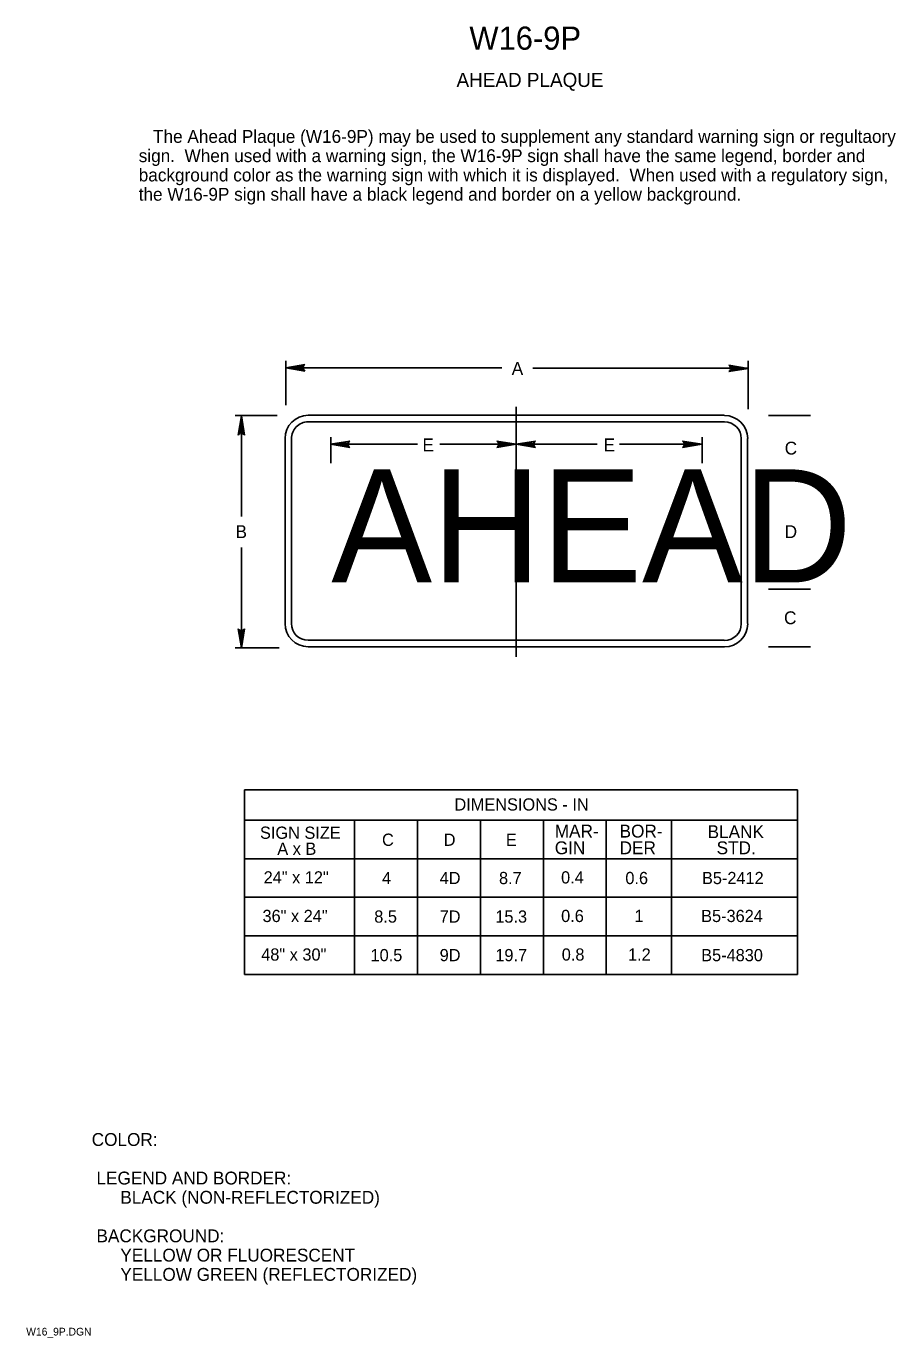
# Model space of a CAD drawing. Extents: x 0.013 to 0.182, y 0.004 to 0.259.
import ezdxf

# ---------------------------------------------------------------- set-up
doc = ezdxf.new("R2010")
doc.units = 0
for name, color, linetype in [('1', 7, 'Continuous'), ('2', 7, 'Continuous'), ('3', 7, 'Continuous')]:
    doc.layers.add(name, color=color, linetype=linetype)

# ---------------------------------------------------------------- blocks, each defined once
blk = doc.blocks.new('RARROW')
at = {"layer": '3'}
for p, q in [((-2.156, 0.285), (-2.2665, 0.384625)), ((-2.2665, 0.384625), (0, 0)), ((0, 0), (-2.2665, -0.379125)), ((-2.156, 0.285), (-2.075625, 0.12075)), ((0, 0), (-2.156, 0.285)), ((-2.14975, -0.2705), (0, 0)), ((-2.075625, 0.12075), (0, 0)), ((0, 0), (-2.074, -0.108)), ((-2.2665, -0.379125), (-2.14975, -0.2705)), ((-2.074, -0.108), (-2.14975, -0.2705))]:
    blk.add_line(p, q, dxfattribs=at)

msp = doc.modelspace()

# ---------------------------------------------------------------- linework, layer by layer
at = {"layer": '1'}
msp.add_line((0.108, 0.185), (0.108, 0.13637), dxfattribs=at)
at = {"layer": '3'}
for p, q in [((0.06313, 0.18534), (0.06313, 0.19396)), ((0.15317, 0.18459), (0.15317, 0.19396)), ((0.10518, 0.19262), (0.06313, 0.19262)), ((0.11123, 0.19257), (0.15312, 0.19257)), ((0.0615, 0.18334), (0.05329, 0.18334)), ((0.0545, 0.16372), (0.0545, 0.18334)), ((0.1485, 0.18338), (0.0675, 0.18338)), ((0.1485, 0.18213), (0.0675, 0.18213)), ((0.1653, 0.18334), (0.15709, 0.18334)), ((0.063, 0.17888), (0.063, 0.14287)), ((0.06425, 0.17888), (0.06425, 0.14287)), ((0.07189, 0.17409), (0.07189, 0.17913)), ((0.108, 0.18088), (0.108, 0.17913)), ((0.14417, 0.17409), (0.14417, 0.17913)), ((0.15175, 0.14287), (0.15175, 0.17888)), ((0.153, 0.14287), (0.153, 0.17888)), ((0.08878, 0.17775), (0.07188, 0.17775)), ((0.09312, 0.17775), (0.108, 0.17775)), ((0.12375, 0.17775), (0.108, 0.17775)), ((0.12812, 0.17775), (0.14417, 0.17775)), ((0.16542, 0.17173), (0.15721, 0.17173)), ((0.0545, 0.15767), (0.0545, 0.13821)), ((0.1653, 0.14959), (0.15709, 0.14959)), ((0.06185, 0.13816), (0.05327, 0.13816)), ((0.0675, 0.13962), (0.1485, 0.13962)), ((0.0675, 0.13837), (0.1485, 0.13837)), ((0.1653, 0.13834), (0.15709, 0.13834)), ((0.05513, 0.1105), (0.16275, 0.1105)), ((0.05513, 0.1105), (0.05513, 0.07462)), ((0.16275, 0.1105), (0.16275, 0.07462)), ((0.16275, 0.10462), (0.05513, 0.10462)), ((0.07653, 0.10454), (0.07653, 0.07461)), ((0.08878, 0.10454), (0.08878, 0.07461)), ((0.10103, 0.10454), (0.10103, 0.07461)), ((0.11328, 0.10454), (0.11328, 0.07461)), ((0.12553, 0.10454), (0.12553, 0.07461)), ((0.13823, 0.10454), (0.13823, 0.07461)), ((0.05513, 0.09713), (0.16275, 0.09713)), ((0.05513, 0.08962), (0.16275, 0.08962)), ((0.05513, 0.08213), (0.16275, 0.08213)), ((0.05513, 0.07462), (0.16275, 0.07462))]:
    msp.add_line(p, q, dxfattribs=at)
for centre, radius, start, end in [((0.06752, 0.17886), 0.00452, 90.2314, 180.2314), ((0.06752, 0.17885), 0.00327, 90.3879, 180.3879), ((0.14856, 0.17884), 0.0045, 0, 90), ((0.14856, 0.17884), 0.00325, 0, 90), ((0.0675, 0.14287), 0.0045, 180, 270), ((0.0675, 0.14287), 0.00325, 180, 270), ((0.14856, 0.14284), 0.0045, 270, 0), ((0.14856, 0.14284), 0.00325, 270, 0)]:
    msp.add_arc(centre, radius, start, end, dxfattribs=at)

# ---------------------------------------------------------------- block references
at = {"layer": '3', "xscale": 0.0016545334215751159, "yscale": 0.0016366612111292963}
for p, rotation in [((0.06313, 0.19262), 180), ((0.0545, 0.18325), 90), ((0.07188, 0.17775), 180), ((0.108, 0.17775), 180), ((0.0545, 0.13812), -90)]:
    msp.add_blockref('RARROW', p, dxfattribs=dict(at, rotation=rotation))
for p in [(0.15313, 0.1925), (0.108, 0.17775), (0.14413, 0.17775)]:
    msp.add_blockref('RARROW', p, dxfattribs=at)

# ---------------------------------------------------------------- texts
at = {"layer": '1'}
for s, height, p in [('W16-9P', 0.0045, (0.09888, 0.2545)), ('AHEAD PLAQUE', 0.0027503, (0.09638, 0.24725)), ('COLOR:', 0.0025, (0.02538, 0.04126)), (' LEGEND AND BORDER:', 0.0024998, (0.02538, 0.03376)), ('      BLACK (NON-REFLECTORIZED)', 0.0024998, (0.02538, 0.03002)), (' BACKGROUND:', 0.0024998, (0.02538, 0.02252)), ('      YELLOW OR FLUORESCENT', 0.0024998, (0.02538, 0.01877)), ('      YELLOW GREEN (REFLECTORIZED)', 0.0024998, (0.02538, 0.01502)), ('W16_9P.DGN', 0.0015, (0.01263, 0.00438))]:
    msp.add_text(s, height=height, dxfattribs=at).set_placement(p)
at = {"layer": '2'}
for s, p in [('   The Ahead Plaque (W16-9P) may be used to supplement any standard warning sign or regultaory', (0.03453, 0.23638)), ('sign.  When used with a warning sign, the W16-9P sign shall have the same legend, border and ', (0.03453, 0.23263)), ('background color as the warning sign with which it is displayed.  When used with a regulatory sign,', (0.03453, 0.22888)), ('the W16-9P sign shall have a black legend and border on a yellow background.', (0.03453, 0.22513))]:
    msp.add_text(s, height=0.0024998, dxfattribs=at).set_placement(p)
at = {"layer": '3'}
for s, height, p in [('A', 0.0025, (0.10712, 0.19125)), ('E', 0.0025, (0.08975, 0.17638)), ('E', 0.0025, (0.125, 0.17638)), ('C', 0.0025, (0.16025, 0.17575)), ('AHEAD', 0.022, (0.072, 0.15088)), ('B', 0.0025, (0.05337, 0.1595)), ('D', 0.0025, (0.16025, 0.1595)), ('C', 0.0025, (0.16012, 0.14275)), ('DIMENSIONS - IN', 0.0023752, (0.09598, 0.1065)), ('SIGN SIZE', 0.002375, (0.05813, 0.101)), ('MAR-', 0.0025, (0.1155, 0.10125)), ('BOR-', 0.0025, (0.12812, 0.10125)), ('BLANK', 0.0025, (0.14525, 0.10113)), ('A x B', 0.002375, (0.0615, 0.09788)), ('C', 0.00238, (0.08188, 0.09963)), ('D', 0.00238, (0.09388, 0.09963)), ('E', 0.00238, (0.106, 0.09963)), ('GIN', 0.0025, (0.1155, 0.098)), ('DER', 0.0025, (0.12812, 0.098)), ('STD.', 0.0025, (0.147, 0.098)), ('24" x 12"', 0.002375, (0.05884, 0.09231)), ('4', 0.00238, (0.08189, 0.09219)), ('4D', 0.002375, (0.0931, 0.09219)), ('8.7', 0.002375, (0.10465, 0.09219)), ('0.4', 0.002375, (0.11673, 0.09231)), ('0.6', 0.002375, (0.12924, 0.09219)), ('B5-2412', 0.002375, (0.14415, 0.09219)), ('36" x 24"', 0.002375, (0.05862, 0.08481)), ('8.5', 0.002375, (0.08037, 0.08469)), ('7D', 0.002375, (0.0931, 0.08469)), ('15.3', 0.002375, (0.10393, 0.08469)), ('0.6', 0.002375, (0.11674, 0.08481)), ('1', 0.00238, (0.13102, 0.08481)), ('B5-3624', 0.002375, (0.14399, 0.08481)), ('48" x 30"', 0.002375, (0.05837, 0.07731)), ('10.5', 0.002375, (0.07965, 0.07719)), ('9D', 0.002375, (0.0931, 0.07719)), ('19.7', 0.002375, (0.10393, 0.07719)), ('0.8', 0.002375, (0.11686, 0.07731)), ('1.2', 0.002375, (0.12976, 0.07731)), ('B5-4830', 0.002375, (0.144, 0.07719))]:
    msp.add_text(s, height=height, dxfattribs=at).set_placement(p)

doc.saveas('drawing.dxf')
